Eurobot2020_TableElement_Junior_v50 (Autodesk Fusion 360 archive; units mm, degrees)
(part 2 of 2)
sketch "Sketch1" plane through (0, 0, 0) normal (1, 0, 0) x axis (0, 1, 0)
  line L1 (0, 5.6673) -> (0, 0)
  line L2 (0, 150) -> (0, 5.6673)
  line L3 (150, 0) -> (-150, 0)
  line L4 (0, -150) -> (0, 0)
  line L5 (25, -137.7498) -> (25, 137.7498)
  line L6 (-25, -137.7498) -> (-25, 137.7498)
  line L7 (15, -139.1941) -> (15, 139.1941)
  line L8 (-15, 139.1941) -> (-15, -139.1941)
  line L9 (15, 20) -> (-15, 20)
  line L10 (-15, -20) -> (15, -20)
  circle C1 centre (0, 0) radius 150
  arc A1 centre (0, 0) radius 140 clockwise from (-15, 139.1941) to (15, 139.1941)
  arc A2 centre (0, 0) radius 140 clockwise from (-25, -137.7498) to (-25, 137.7498)
  arc A3 centre (0, 0) radius 140 clockwise from (25, 137.7498) to (25, -137.7498)
  arc A4 centre (0, 0) radius 140 clockwise from (15, -139.1941) to (-15, -139.1941)
  point P1 (0, 0)
  point P2 (0, 0)
  point P3 (0, 0)
  point P5 (0, 150)
  point P6 (-150, 0)
  point P7 (150, 0)
  point P10 (0, 77.8337)
  point P11 (0, 0)
  point P12 (0, -150)
  point P13 (0, 0)
  point P18 (0, 0)
  point P17 (-25, -137.7498)
  point P19 (-25, -137.7498)
  point P20 (0, 0)
  point P15 (25, -137.7498)
  point P21 (25, -137.7498)
  point P24 (0, -75)
  point P25 (0, 0)
  point P26 (-15, 20)
  point P27 (15, 20)
  point P28 (15, -20)
  point P29 (-15, -20)
  coincident P1 P2
  coincident P1 P3
  vertical L1
  coincident C1 P5
  parallel L1 L2
  coincident C1 P6
  coincident C1 P7
  horizontal L3
  coincident P2 L3
  midpoint L2 P10
  coincident P2 P11
  coincident C1 P12
  perpendicular L3 L4
  coincident P1 P13
  vertical L6
  coincident P2 P18
  coincident P17 P19
  coincident P2 P20
  coincident P15 P21
  equal A1 A2
  equal A1 A3
  midpoint L4 P24
  coincident P2 P25
  tangent A3 A4
  perpendicular L3 L7
  parallel L6 L8
  coincident L8 P26
  coincident L7 P27
  perpendicular L7 L9
  coincident L7 P28
  coincident L8 P29
  perpendicular L8 L10
  dimension "d1" diameter C1 = 300
  dimension "d11" distance C1 A3 = 10
  dimension "d13" distance L5 L7 = 10
  dimension "d14" distance L6 L8 = 10
  dimension "d15" distance P18 L7 = 15
  dimension "d16" distance P20 L8 = 15
  dimension "d17" distance P13 L10 = 20
  dimension "d18" distance P2 L9 = 20
extrude "Extrude1" new body sketch "Sketch1" profile of C1 A1 L5 L6 A2 A3 A4 L7 L8 L9 L10 along normal blind 20
extrude "Extrude1" new body sketch "Sketch1" profile of C1 A1 L5 L6 A2 A3 A4 L7 L8 L9 L10 against normal blind 3
extrude "Extrude1" sketch "Sketch1" profile of C1 A1 L5 L6 A2 A3 A4 L7 L8 L9 L10 blind 3
as_built_joint "As-built1"
hole "Hole1" HoleDepth 70 HoleDiameter 7 TipAngle 118
sketch "Sketch3" plane through (0, 0, 0) normal (1, 0, 0) x axis (0, 1, 0)
  point P1 (0, 0)
  point P2 (0, 0)
  coincident P1 P2
hole "Hole2" HoleDepth 70 HoleDiameter 6 TipAngle 118
sketch "Sketch1" plane through (23, 0, 0) normal (1, 0, 0) x axis (0, 1, 0)
  circle C1 centre (0, 0) radius 150
  point P1 (0, 0)
  point P3 (0, 0)
  coincident P1 P3
hole "Hole2" HoleDepth 70 HoleDiameter 6 TipAngle 118 CSDiameter 14 CSAngle 90
sketch "Sketch2" plane through (0, 0, 0) normal (1, 0, 0) x axis (0, 1, 0)
  circle C1 centre (0, 0) radius 3.5
  circle C2 centre (0, 0) radius 2
  point P1 (0, 0)
  point P2 (0, 0)
  coincident P1 P2
  concentric C1 C2
  dimension "d55" diameter C1 = 7
  dimension "d56" diameter C2 = 4
extrude "Extrude1" new body sketch "Sketch2" along normal blind 20
as_built_joint "As-built2"
sketch "Sketch1" plane through (0, 0, 0) normal (0, 1, 0) x axis (1, 0, 0)
  line L1 (22.3531, 0) -> (-23.5815, 0)
  line L2 (22.3531, -4.2842) -> (22.3531, 0)
  line L3 (20, -1.7) -> (22.3531, -4.2842)
  line L4 (-23.5815, -1.7) -> (20, -1.7)
  line L5 (-23.5815, 0) -> (-23.5815, -1.7)
  line L6 (20, -150) -> (20, 150)
  point P1 (0, 0)
  point P5 (20, -1.7)
  horizontal L1
  perpendicular L1 L2
  perpendicular L2 L4
  coincident P1 L1
  coincident P5 L6
  vertical L5
  dimension "d59" distance L1 L4 = 1.7
revolve "Revolve1" sketch "Sketch1" AlongAngle 360
thread "Thread1" ThreadOffset 0 ThreadLength 21
sketch "Sketch2" plane through (0, 0, 0) normal (0, 1, 0) x axis (1, 0, 0)
  line L1 (-13.9609, -1.9748) -> (-23.5815, 0)
  line L2 (-23.5815, -1.9748) -> (-13.9609, -1.9748)
  line L3 (-23.5815, 0) -> (-23.5815, -1.9748)
  line L4 (-23.5815, 0) -> (0, 0)
  line L5 (-23.5815, 0.8397) -> (-23.5815, -0.8535)
  point P1 (0, 0)
  point P5 (0, 0)
  point P2 (-23.5815, 0)
  vertical L3
  horizontal L2
  coincident P1 P5
  horizontal L4
  coincident P2 L5
revolve "Revolve2" sketch "Sketch2" AlongAngle 360
offset_faces "OffsetFaces2" distance -0.43
offset_faces "OffsetFaces3" distance -1
sketch "Sketch3" plane through (22.3531, 0, 0) normal (1, 0, 0) x axis (0, 1, 0)
  line L1 (0, 2) -> (0, 0)
  line L2 (-0.4, 2) -> (0, 2)
  line L3 (-0.4, 0.4) -> (-0.4, 2)
  line L4 (-2, 0.4) -> (-0.4, 0.4)
  line L5 (-2, 0) -> (-2, 0.4)
  line L6 (0, 0) -> (-2, 0)
  line L7 (0.4, 0.4) -> (0.4, 2)
  line L8 (2, 0.4) -> (0.4, 0.4)
  line L9 (2, 0) -> (2, 0.4)
  line L10 (0.4, 2) -> (0, 2)
  line L11 (0.4, -2) -> (0, -2)
  line L12 (0.4, -0.4) -> (0.4, -2)
  line L13 (2, -0.4) -> (0.4, -0.4)
  line L14 (2, 0) -> (2, -0.4)
  line L15 (-0.4, -2) -> (0, -2)
  line L16 (-0.4, -0.4) -> (-0.4, -2)
  line L17 (-2, -0.4) -> (-0.4, -0.4)
  line L18 (-2, 0) -> (-2, -0.4)
  circle C1 centre (0, 0) radius 2.7989
  point P2 (0, 0)
  point P3 (0, 0)
  point P4 (0, 2)
  point P13 (0, 2)
  point P5 (-0.4, 2)
  point P9 (0.4, 2)
  point P6 (-0.4, 0.4)
  point P10 (0.4, 0.4)
  point P7 (-2, 0.4)
  point P11 (2, 0.4)
  point P8 (-2, 0)
  point P12 (2, 0)
  point P19 (0, -2)
  point P20 (-0.4, -2)
  point P21 (-0.4, -0.4)
  point P22 (-2, -0.4)
  point P23 (-2, 0)
  point P15 (0.4, -2)
  point P16 (0.4, -0.4)
  point P17 (2, -0.4)
  point P18 (2, 0)
  point P14 (0, -2)
  coincident P2 P3
  vertical L1
  perpendicular L1 L2
  perpendicular L2 L3
  perpendicular L1 L4
  perpendicular L2 L5
  horizontal L6
  equal L1 L6
  equal L2 L5
  symmetric P4 L1 P13
  symmetric L1 P5 P9
  symmetric L1 P6 P10
  symmetric L1 P7 P11
  symmetric L1 P8 P12
  symmetric P4 L6 P19
  symmetric P5 L6 P20
  symmetric P6 L6 P21
  symmetric P7 L6 P22
  symmetric P8 L6 P23
  symmetric L6 P9 P15
  symmetric L6 P10 P16
  symmetric L6 P11 P17
  symmetric L6 P12 P18
  symmetric L6 P13 P14
  dimension "d69" distance P4 P5 = 0.4
  dimension "d70" distance P7 P8 = 0.4
  dimension "d71" distance P3 P4 = 2
extrude "Extrude2" cut sketch "Sketch3" profile of L2 L3 L4 L5 L7 L8 L9 L10 L11 L12 L13 L14 L15 L16 L17 L18 against normal blind 1 taper -25
joint "Assemble1" alignAngle 0 alignOffsetX 0 alignOffsetY 0 alignOffsetZ 0.5
sketch "Sketch1" plane through (-3, 0, 0) normal (-1, 0, 0) x axis (0, -1, 0)
  circle C1 centre (0, 0) radius 3
  circle C2 centre (0, 0) radius 150
  circle C3 centre (0, 0) radius 5
  circle C4 centre (0, 0) radius 2
  point P1 (0, 0)
  point P3 (0, 0)
  coincident P1 P3
  concentric C1 C4
  dimension "d86" diameter C4 = 4
  dimension "d87" diameter C3 = 10
extrude "Extrude1" new body sketch "Sketch1" profile of C1 C3 C4 along normal blind 0.8
extrude "Extrude2" new body of existing geometry blind 0.8
as_built_joint "As-built3"
sketch "Sketch1" plane through (23, 0, 0) normal (1, 0, 0) x axis (0, 1, 0)
  circle C1 centre (0, 0) radius 150
extrude "Extrude1" new body sketch "Sketch1" along normal blind 0.3
decal "Decal1"
sketch "Sketch1" plane through (0, 0, 0) normal (1, 0, 0) x axis (0, 1, 0)
  line L1 (0, 32.5) -> (0, 0)
  line L2 (0, -127.5) -> (0, 0)
  line L3 (-15, 20) -> (15, 20)
  circle C1 centre (0, 32.5) radius 12.5
  circle C2 centre (0, -127.5) radius 12.5
  arc A1 centre (0, 0) radius 140 clockwise from (15, -139.1941) to (-15, -139.1941)
  point P1 (0, 0)
  point P2 (0, 0)
  point P3 (0, 32.5)
  point P4 (0, 32.5)
  point P5 (0, 0)
  point P6 (0, -127.5)
  point P7 (0, -127.5)
  point P8 (0, -140)
  point P9 (0, 20)
  coincident P1 P2
  vertical L1
  coincident P3 P4
  coincident P1 P5
  parallel L1 L2
  coincident P6 P7
  equal C1 C2
  coincident C2 P8
  coincident C1 P9
  coincident L1 P9
  coincident P9 L3
  coincident L2 P8
  coincident P8 A1
  dimension "d94" diameter C1 = 25
extrude "Extrude1" new body sketch "Sketch1" profile of C1 C2 along normal blind 18
as_built_joint "As-built4"
split_face "SplitFace1"
split_face "SplitFace1"
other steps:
split_face "SplitFace1"
split_face "SplitFace1"
create_component "CreateComponent1"
create_component "CreateComponent2"
create_component "CreateComponent3"
create_component "CreateComponent4"
create_component "CreateComponent5"
joint_origin "JointOrigin1" OffsetX 0 OffsetY 0 OffsetZ 0 AngleZ 0
joint_origin "JointOrigin1" OffsetX 0 OffsetY 0 OffsetZ 0 AngleZ 0
create_component "CreateComponent6"
create_component "CreateComponent7"
create_component "CreateComponent8"

design "Edge Beacon Right" references "EdgeBeacons_Base", "EdgeBeacons_LargeBorder", "EdgeBeacons_SmallBorder"
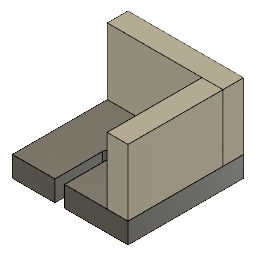
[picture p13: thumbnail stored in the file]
component_insert "Component Insert1"
ground "Ground1"
component_insert "Component Insert2"
component_insert "Component Insert4"
joint "Assemble1" OffsetX 0 OffsetY 0 OffsetZ 0 AngleZ 0 OffsetX 0 OffsetY 0 OffsetZ 0 AngleZ 0 alignAngle -90 alignOffsetX 0 alignOffsetY 0 alignOffsetZ 0
joint "Assemble2" OffsetX 0 OffsetY 0 OffsetZ 0 AngleZ 0 OffsetX 0 OffsetY 0 OffsetZ 0 AngleZ 0 alignAngle 0 alignOffsetX 0 alignOffsetY 0 alignOffsetZ 0

design "MiddleBeaconTop"
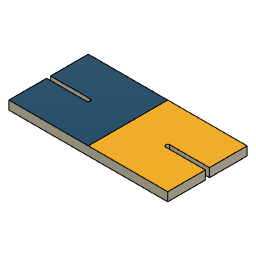
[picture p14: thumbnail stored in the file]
work_plane "WorkPlane1" AlongDistance 1000
sketch "Sketch1" plane through (0, 1000, 0) normal (0, 1, 0) x axis (1, 0, 0)
  line L1 (200, -100) -> (-200, -100)
  line L2 (200, 100) -> (200, -100)
  line L3 (-200, 100) -> (200, 100)
  line L4 (-200, -100) -> (-200, 100)
  line L5 (200, 100) -> (-200, -100)
  line L6 (-200, 100) -> (200, -100)
  line L7 (-100, -5) -> (-200, -5)
  line L8 (-200, 5) -> (-100, 5)
  line L9 (-100, 0) -> (-200, 0)
  line L10 (100, 5) -> (200, 5)
  line L11 (200, -5) -> (100, -5)
  line L12 (100, 0) -> (200, 0)
  arc A1 centre (-100, 0) radius 5 clockwise from (-100, 5) to (-100, -5)
  arc A2 centre (-200, 0) radius 5 clockwise from (-200, -5) to (-200, 5)
  arc A3 centre (100, 0) radius 5 clockwise from (100, -5) to (100, 5)
  arc A4 centre (200, 0) radius 5 clockwise from (200, 5) to (200, -5)
  point P6 (0, 0)
  point P1 (0, 0)
  point P11 (-200, 0)
  point P17 (200, 0)
  point P4 (200, 100)
  point P5 (-200, 100)
  point P3 (200, -100)
  point P12 (-100, 0)
  perpendicular L1 L2
  parallel L1 L3
  parallel L2 L4
  horizontal L1
  coincident L5 P6
  coincident L6 P6
  coincident P1 P6
  tangent L7 A1
  tangent A1 L8
  parallel L7 L8
  tangent L8 A2
  tangent L7 A2
  perpendicular L4 L9
  midpoint L4 P11
  tangent L10 A3
  tangent A3 L11
  parallel L10 L11
  tangent L11 A4
  tangent L10 A4
  perpendicular L2 L12
  midpoint L2 P17
  equal A1 A3
  equal L9 L12
  dimension "d2" distance P4 P5 = 400
  dimension "d3" distance P3 P4 = 200
  dimension "d4" distance P11 P12 = 100
  dimension "d5" radius A1 = 5
extrude "Extrude1" new body sketch "Sketch1" profile of L1 L2 L3 L4 L7 A1 L8 L10 A3 L11 against normal blind 22
work_plane "WorkPlane2"
split_face "SplitFace1"

design "MiddleBeaconVertSupport2"
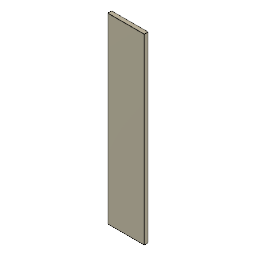
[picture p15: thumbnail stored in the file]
sketch "Sketch1"
  dimension "d1" = 1000
  dimension "d2" = 200
extrude "Extrude1" new body sketch "Sketch1" distance 22

design "manchonBleu"
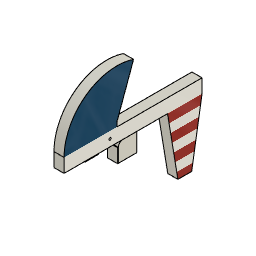
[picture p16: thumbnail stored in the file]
sketch "Sketch1" plane through (0, 0, 0) normal (1, 0, 0) x axis (0, 1, 0)
  line L1 (15, 15) -> (15, 25)
  line L2 (200, 15) -> (15, 15)
  line L3 (-100, -15) -> (125, -15)
  line L4 (-100, 15) -> (-100, -15)
  line L5 (200, 15) -> (200, -15)
  line L6 (177.5, -150) -> (200, -15)
  line L7 (147.5, -150) -> (177.5, -150)
  line L8 (125, -15) -> (147.5, -150)
  line L9 (0, 0) -> (200, 0)
  line L10 (15, 15) -> (-15, 15)
  line L11 (0, 15) -> (0, 0)
  line L12 (51.101, 124.1866) -> (15, 25)
  circle C1 centre (0, 0) radius 2.5
  circle C2 centre (15, 15) radius 115
  point P1 (0, 0)
  point P2 (0, 0)
  point P13 (200, 0)
  point P14 (0, 0)
  point P15 (0, 0)
  point P16 (0, 15)
  point P9 (-100, 15)
  point P5 (15, 15)
  point P17 (15, 15)
  point P18 (51.101, 124.1866)
  point P7 (125, -15)
  point P10 (200, -15)
  point P11 (177.5, -150)
  point P12 (147.5, -150)
  point P8 (-100, -15)
  point P4 (15, 25)
  coincident P1 P2
  perpendicular L1 L2
  horizontal L3
  perpendicular L3 L4
  vertical L5
  equal L4 L5
  parallel L3 L7
  equal L6 L8
  midpoint L5 P13
  coincident P1 P14
  horizontal L9
  coincident P1 P15
  midpoint L10 P16
  vertical L11
  coincident L2 P9
  horizontal L2
  horizontal L10
  equal L4 L10
  coincident P5 P17
  coincident P9 C2
  coincident C2 P18
  dimension "d1" diameter C1 = 5
  dimension "d2" distance P1 L4 = 100
  dimension "d4" distance P2 L5 = 200
  dimension "d8" distance P7 P10 = 75
  dimension "d9" distance P11 P12 = 30
  dimension "d11" distance P8 P9 = 30
  dimension "d12" distance P4 P5 = 10
  dimension "d22" distance L7 L9 = 150
  dimension "d23" angle L2 L12 = 70
  dimension "d36" OffsetX = 0
  dimension "d37" OffsetY = 0
  dimension "d38" OffsetZ = 0
  dimension "d39" AngleZ = 0
  dimension "d48" OffsetX = 0
  dimension "d49" OffsetY = 0
  dimension "d50" OffsetZ = 0
  dimension "d51" AngleZ = 0
extrude "Extrude1" new body sketch "Sketch1" profile of C1 L1 L2 L3 L4 L5 L6 L7 L8 C2 L12 along normal blind 22
sketch "Sketch1" plane through (0, 0, 0) normal (1, 0, 0) x axis (0, 0, -1)
  line L1 (55, 15) -> (15, 15)
  line L2 (55, 55) -> (55, 15)
  line L3 (15, 55) -> (55, 55)
  line L4 (15, 15) -> (15, 55)
  line L5 (15, -100) -> (15, 125)
  line L6 (25, 15) -> (15, 15)
  arc A1 centre (25, 25) radius 10 clockwise from (25, 15) to (15, 25)
  point P8 (25, 15)
  point P9 (15, 25)
  point P1 (0, 0)
  horizontal L1
  vertical L2
  horizontal L3
  vertical L4
  coincident L1 P8
  perpendicular L5 L6
  tangent L6 A1
  coincident L4 P9
  tangent L4 A1
  dimension "d24" distance P1 L1 = 15
  dimension "d25" distance P1 L4 = 15
  dimension "d26" distance P1 L5 = 15
  dimension "d27" distance L4 P8 = 10
  dimension "d28" distance L1 L3 = 40
  dimension "d29" distance L2 L4 = 40
  dimension "d32" OffsetX = 0
  dimension "d33" OffsetY = 0
  dimension "d34" OffsetZ = 0
  dimension "d35" AngleZ = 0
  dimension "d44" OffsetX = 0
  dimension "d45" OffsetY = 0
  dimension "d46" OffsetZ = 0
  dimension "d47" AngleZ = 0
extrude "Extrude1" new body sketch "Sketch1" profile of L1 L2 L3 L4 L5 A1 along normal blind 22
joint "Assemble1" alignAngle 0 alignOffsetX -25 alignOffsetY -28 alignOffsetZ 0
decal "Decal1"
decal "Decal2"
sketch "Sketch1" plane through (0, 18, 0) normal (0, -1, 0) x axis (1, 0, 0)
  line L1 (0, -55) -> (0, -25)
  line L2 (22, -55) -> (0, -55)
  line L3 (22, -25) -> (22, -55)
  line L4 (0, -25) -> (22, -25)
extrude "Extrude1" new body sketch "Sketch1" along normal blind 1.5 named "d52_1"
sketch "Sketch2" plane through (0, 0, -15) normal (0, 0, -1) x axis (1, 0, 0)
  line L1 (0, -125) -> (0, 100)
  line L2 (22, -125) -> (0, -125)
  line L3 (22, 100) -> (22, -125)
  line L4 (0, 100) -> (22, 100)
  line L5 (0, 55) -> (0, 25)
  line L6 (22, 55) -> (0, 55)
  line L7 (22, 25) -> (22, 55)
  line L8 (0, 25) -> (22, 25)
extrude "Extrude2" new body sketch "Sketch2" profile of L1 L3 L5 L6 L7 L8 along normal blind 1.5 named "d63_1"
joint_origin "JointOrigin1" OffsetX 0 named "d66_1" OffsetY 0 named "d67_1" OffsetZ 0 named "d68_1" AngleZ 0 named "d69_1"
joint_origin "JointOrigin2" OffsetX 0 named "d78_1" OffsetY 0 named "d79_1" OffsetZ 0 named "d80_1" AngleZ 0 named "d81_1"
remove_body "RemoveBody1"
joint "Assemble2" alignAngle 0 alignOffsetX 0 alignOffsetY 0 alignOffsetZ 0
base_feature "Base Feature"
joint "Assemble3" alignAngle 0 alignOffsetX 0 alignOffsetY 45 alignOffsetZ 0
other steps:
create_component "CreateComponent1"
create_component "CreateComponent2"
joint_origin "JointOrigin3" OffsetX 0 OffsetY 0 OffsetZ 0 AngleZ 0
joint_origin "JointOrigin3" OffsetX 0 OffsetY 0 OffsetZ 0 AngleZ 0
create_component "CreateComponent3"
joint_origin "JointOrigin1" OffsetX 0 OffsetY 0 OffsetZ 0 AngleZ 0
joint_origin "JointOrigin3" OffsetX 0 OffsetY 0 OffsetZ 0 AngleZ 0
joint_origin "JointOrigin4" OffsetX 0 OffsetY 0 OffsetZ 0 AngleZ 0
joint_origin "JointOrigin4" OffsetX 0 OffsetY 0 OffsetZ 0 AngleZ 0

design "Rocher"
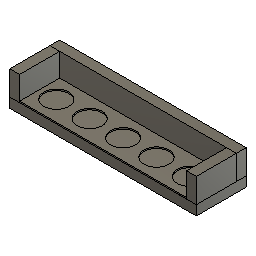
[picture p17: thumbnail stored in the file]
sketch "Sketch1" plane through (0, 0, 0) normal (0, 1, 0) x axis (1, 0, 0)
  line L1 (209.5, 0) -> (-209.5, 0)
  line L2 (209.5, 112) -> (209.5, 0)
  line L3 (-209.5, 112) -> (209.5, 112)
  line L4 (-209.5, 0) -> (-209.5, 112)
  point P6 (0, 0)
  horizontal L1
  vertical L2
  horizontal L3
  vertical L4
  coincident L1 P6
  dimension "d11" distance L2 L4 = 419 (= "375 mm + ( ( 22 * 2 ) * 1 mm )")
  dimension "d12" distance L2 P6 = 209.5 (= "d11 / 2")
  dimension "d13" distance L1 L3 = 112 (= "90 mm + 22 mm")
extrude "Extrude1" new body sketch "Sketch1" against normal blind 22
sketch "Sketch1" plane through (0, 0, 0) normal (0, 1, 0) x axis (-1, 0, 0)
  line L1 (-209.5, -112) -> (209.5, -112)
  line L2 (-209.5, -90) -> (-209.5, -112)
  line L3 (209.5, -90) -> (-209.5, -90)
  line L4 (209.5, -112) -> (209.5, -90)
  line L5 (-209.5, -112) -> (-209.5, 0)
  line L6 (209.5, 0) -> (209.5, -112)
  line L7 (209.5, -112) -> (-209.5, -112)
  horizontal L1
  vertical L2
  horizontal L3
  vertical L4
  collinear L2 L5
  collinear L4 L6
  collinear L1 L7
  dimension "d17" distance L1 L3 = 22
extrude "Extrude1" new body sketch "Sketch1" along normal blind 55
sketch "Sketch1" plane through (0, 0, 0) normal (0, 1, 0) x axis (-1, 0, 0)
  line L1 (-147, 0) -> (147, 0)
  line L2 (147, -90) -> (125, -90)
  line L3 (147, 0) -> (147, -90)
  line L4 (125, 0) -> (147, 0)
  line L5 (125, -90) -> (125, 0)
  line L6 (-147, 0) -> (147, 0)
  line L7 (147, -112) -> (-147, -112)
  line L8 (147, 0) -> (147, -112)
  line L9 (147, -90) -> (-147, -90)
  line L10 (147, 0) -> (147, -112)
  line L11 (-147, -112) -> (-147, 0)
  line L12 (147, -112) -> (-147, -112)
  horizontal L2
  vertical L3
  horizontal L4
  vertical L5
  collinear L4 L6
  collinear L3 L8
  collinear L2 L9
  dimension "d20" distance L3 L5 = 22
extrude "Extrude1" new body sketch "Sketch1" profile of L1 L2 L3 L4 L5 L6 L8 L9 L10 along normal blind 55
sketch "Sketch1" plane through (0, 0, 0) normal (0, 1, 0) x axis (-1, 0, 0)
  line L1 (209.5, 0) -> (209.5, -112)
  line L2 (-209.5, 0) -> (209.5, 0)
  line L3 (-209.5, -112) -> (-209.5, 0)
  line L4 (209.5, -112) -> (-209.5, -112)
  line L5 (-187.5, -90) -> (-209.5, -90)
  line L6 (-187.5, 0) -> (-187.5, -90)
  line L7 (-209.5, 0) -> (-187.5, 0)
  line L8 (-209.5, -90) -> (-209.5, 0)
  line L9 (209.5, -90) -> (-209.5, -90)
  horizontal L5
  vertical L6
  horizontal L7
  vertical L8
  collinear L2 L7
  collinear L5 L9
  collinear L3 L8
  dimension "d23" distance L6 L8 = 22
extrude "Extrude1" new body sketch "Sketch1" profile of L2 L3 L5 L6 L7 L8 L9 along normal blind 55
joint "Assemble1" alignAngle 0 alignOffsetX 0 alignOffsetY 0 alignOffsetZ 0
joint "Assemble2" alignAngle 0 alignOffsetX 0 alignOffsetY 0 alignOffsetZ 0
joint "Assemble3" alignAngle 0 alignOffsetX 0 alignOffsetY 0 alignOffsetZ 0
ground "Ground1"
sketch "Sketch1" plane through (0, 0, 0) normal (0, 1, 0) x axis (-1, 0, 0)
  line L1 (209.5, 0) -> (209.5, -112)
  line L2 (-209.5, 0) -> (209.5, 0)
  line L3 (-209.5, -112) -> (-209.5, 0)
  line L4 (209.5, -112) -> (-209.5, -112)
  line L5 (-209.5, -90) -> (209.5, -90)
  line L6 (187.5, -90) -> (187.5, 0)
  line L7 (-187.5, 0) -> (-187.5, -90)
  circle C1 centre (150, -45) radius 28
  circle C2 centre (75, -45) radius 28
  circle C3 centre (0, -45) radius 28
  circle C4 centre (-75, -45) radius 28
  circle C5 centre (-150, -45) radius 28
  point P12 (150, -45)
  point P13 (75, -45)
  point P14 (0, -45)
  point P15 (-75, -45)
  point P16 (-150, -45)
  dimension "d62" diameter C1 = 56
  dimension "d67" distance L6 P12 = 37.5
  dimension "d68" distance P12 P13 = 75 (= "d67 * 2")
  dimension "d69" distance P13 P14 = 75 (= "d68")
  dimension "d70" distance P14 P15 = 75 (= "d69")
  dimension "d72" distance L2 P12 = 45
  dimension "d73" distance L2 P13 = 45
  dimension "d74" distance L2 P14 = 45
  dimension "d75" distance L2 P15 = 45
  dimension "d90" diameter C5 = 56 (= "d62")
  dimension "d91" distance P15 P16 = 75
  dimension "d92" distance L7 P16 = 37.5
  dimension "d93" diameter C2 = 56 (= "d62")
  dimension "d94" diameter C3 = 56 (= "d62")
  dimension "d95" diameter C4 = 56
extrude "Extrude1" new body sketch "Sketch1" profile of L2 L5 L6 L7 C1 C2 C3 C4 C5 along normal blind 3
joint "Assemble4" alignAngle 180 alignOffsetX 0 alignOffsetY 0 alignOffsetZ 0
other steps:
create_component "CreateComponent1"
create_component "CreateComponent2"
create_component "CreateComponent3"
create_component "CreateComponent4"
joint_origin "JointOrigin1" OffsetX 0 OffsetY 0 OffsetZ 0 AngleZ 0
joint_origin "JointOrigin1" OffsetX 0 OffsetY 0 OffsetZ 0 AngleZ 0
joint_origin "JointOrigin1" OffsetX 0 OffsetY 0 OffsetZ 0 AngleZ 0
joint_origin "JointOrigin2" OffsetX 0 OffsetY 0 OffsetZ 0 AngleZ 0
joint_origin "JointOrigin1" OffsetX 0 OffsetY 0 OffsetZ 0 AngleZ 0
joint_origin "JointOrigin3" OffsetX 0 OffsetY 0 OffsetZ 0 AngleZ 0
create_component "CreateComponent5"
joint_origin "JointOrigin1" OffsetX 0 OffsetY 0 OffsetZ 0 AngleZ 0
joint_origin "JointOrigin2" OffsetX 0 OffsetY 0 OffsetZ 0 AngleZ 0

design "Balise Rouge"
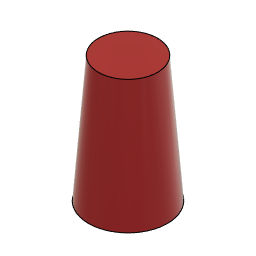
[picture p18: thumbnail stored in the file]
sketch "Sketch1" plane through (0, 0, 0) normal (1, 0, 0) x axis (0, 0, -1)
  line L1 (-36, 0) -> (0, 0)
  line L2 (-27, 115) -> (-36, 0)
  line L3 (0, 115) -> (-27, 115)
  line L4 (0, 0) -> (0, 115)
  line L5 (-25.6128, 113.5) -> (0, 113.5)
  line L6 (-34.4954, 0) -> (-25.6128, 113.5)
  line L7 (0, 0) -> (-34.4954, 0)
  point P1 (0, 0)
  point P2 (0, 0)
  point P6 (0, 0)
  point P7 (0, 113.5)
  point P10 (0, 0)
  point P4 (-27, 115)
  point P5 (0, 115)
  point P3 (-36, 0)
  coincident P1 P2
  horizontal L1
  parallel L1 L3
  coincident P1 P6
  perpendicular L1 L4
  coincident L4 P7
  perpendicular L4 L5
  coincident L4 P10
  perpendicular L4 L7
  collinear L1 L7
  parallel L2 L6
  dimension "d1" distance P4 P5 = 27 (= "( 54 / 2 ) * 1 mm")
  dimension "d2" distance L1 L3 = 115
  dimension "d3" distance P2 P3 = 36 (= "( 72 / 2 ) * 1 mm")
  dimension "d5" distance L3 L5 = 1.5
  dimension "d6" distance L2 L6 = 1.5
revolve "Revolve1" sketch "Sketch1" AlongAngle 360

design "taquet"
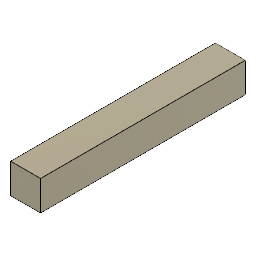
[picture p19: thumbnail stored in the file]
sketch "Sketch1" plane through (0, 0, 0) normal (0, 1, 0) x axis (1, 0, 0)
  line L1 (11, 150) -> (-11, 150)
  line L2 (11, 0) -> (11, 150)
  line L3 (11, 150) -> (-11, 0)
  line L4 (-11, 150) -> (-11, 0)
  point P1 (0, 0)
  horizontal L1
  vertical L2
  horizontal L3
  vertical L4
  coincident P1 L3
  dimension "d1" distance L2 L4 = 22
  dimension "d2" distance P1 L4 = 11 (= "d1 / 2")
  dimension "d3" = 150
extrude "Extrude1" new body sketch "Sketch1" along normal blind 22

design "ROUE_MINI_V3_ASSEMBLAGE" references "ROUE_V3"
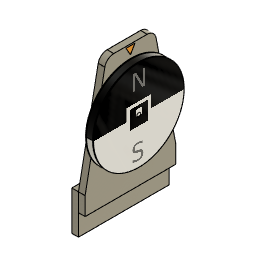
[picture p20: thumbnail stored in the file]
sketch "Sketch1" plane through (0, 0, 0) normal (1, 0, 0) x axis (0, 1, 0)
  line L1 (-150, 0) -> (0, 0)
  line L2 (0, 420) -> (-80, 420)
  line L3 (0, 0) -> (0, 420)
  line L4 (-150, 60) -> (-80, 420)
  line L5 (-150, 0) -> (-150, 60)
  line L6 (150, 0) -> (0, 0)
  line L7 (150, 0) -> (150, 60)
  line L8 (150, 60) -> (80, 420)
  line L9 (0, 420) -> (80, 420)
  point P1 (0, 0)
  point P2 (0, 0)
  point P6 (0, 0)
  point P8 (0, 0)
  point P3 (-150, 0)
  point P9 (150, 0)
  point P4 (-80, 420)
  point P11 (80, 420)
  point P5 (0, 420)
  point P12 (0, 420)
  point P7 (-150, 60)
  point P10 (150, 60)
  point P13 (0, 230)
  coincident P1 P2
  horizontal L1
  parallel L1 L2
  coincident P1 P6
  perpendicular L1 L3
  perpendicular L1 L5
  symmetric P2 L3 P8
  symmetric P3 L3 P9
  symmetric P4 L3 P11
  symmetric P5 L3 P12
  symmetric L3 P7 P10
  coincident L3 P13
  dimension "d1" distance P2 P3 = 150
  dimension "d2" distance P4 P5 = 80
  dimension "d3" distance P3 P7 = 60
  dimension "d4" distance L1 L2 = 420
  dimension "d5" distance L6 P13 = 230
extrude "Extrude1" new body sketch "Sketch1" profile of L1 L2 L4 L5 L6 L7 L8 L9 along normal blind 22
hole "Hole1" HoleDepth 100 HoleDiameter 3 TipAngle 118
fillet "Fillet1" radius 30
sketch "Sketch1" plane through (0, 0, 0) normal (-1, 0, 0) x axis (0, -1, 0)
  line L1 (-150, 60) -> (-84.7199, 395.7261)
  line L2 (-150, 0) -> (-150, 60)
  line L3 (150, 0) -> (-150, 0)
  line L4 (150, 60) -> (150, 0)
  line L5 (84.7199, 395.7261) -> (150, 60)
  line L6 (-55.2715, 420) -> (55.2715, 420)
  line L7 (-11, 213.2177) -> (-11, 0)
  line L8 (-86.7983, 136.8472) -> (-11, 136.8472)
  line L9 (-86.7983, 117.0762) -> (-86.7983, 136.8472)
  line L10 (-11, 117.0762) -> (-86.7983, 117.0762)
  line L11 (-11, 136.8472) -> (-11, 117.0762)
  line L12 (-13, 136.8472) -> (-11, 136.8472)
  line L13 (-13, 117.0762) -> (-13, 136.8472)
  line L14 (-11, 117.0762) -> (-13, 117.0762)
  line L15 (-11, 136.8472) -> (-11, 117.0762)
  circle C1 centre (0, 230) radius 1.5
  arc A1 centre (-55.2715, 390) radius 30 clockwise from (-84.7199, 395.7261) to (-55.2715, 420)
  arc A2 centre (55.2715, 390) radius 30 clockwise from (55.2715, 420) to (84.7199, 395.7261)
  point P13 (-11, 0)
  point P15 (-11, 136.8472)
  point P20 (-13, 117.0762)
  point P1 (0, 0)
  coincident L3 P13
  perpendicular L3 L7
  horizontal L8
  vertical L9
  horizontal L10
  vertical L11
  coincident L7 P15
  horizontal L12
  vertical L13
  horizontal L14
  vertical L15
  coincident L10 P20
  dimension "d31" distance L11 L13 = 2
  dimension "d32" distance P1 L7 = 11 (= "( 22 / 2 ) * 1 mm")
extrude "Extrude1" new body sketch "Sketch1" profile of L8 L9 L10 L11 L12 L13 L14 L15 along normal blind 2
extrude "Extrude2" add sketch "Sketch1" profile of L8 L10 L11 L12 L13 L14 L15 along normal blind 60
ground "Ground1"
sketch "Sketch1" plane through (0, 0, 0) normal (-1, 0, 0) x axis (0, -1, 0)
  line L1 (-150, 60) -> (-84.7199, 395.7261)
  line L2 (-150, 0) -> (-150, 60)
  line L3 (150, 0) -> (-150, 0)
  line L4 (150, 60) -> (150, 0)
  line L5 (84.7199, 395.7261) -> (150, 60)
  line L6 (-55.2715, 420) -> (55.2715, 420)
  line L7 (150, 0) -> (150, 60)
  line L8 (-150, 0) -> (-150, 60)
  line L9 (150, 60) -> (-150, 60)
  line L10 (150, -70) -> (150, 0)
  line L11 (-150, -70) -> (150, -70)
  line L12 (-150, 0) -> (-150, -70)
  circle C1 centre (0, 230) radius 1.5
  arc A1 centre (-55.2715, 390) radius 30 clockwise from (-84.7199, 395.7261) to (-55.2715, 420)
  arc A2 centre (55.2715, 390) radius 30 clockwise from (55.2715, 420) to (84.7199, 395.7261)
  point P15 (-150, 60)
  point P17 (-150, 60)
  point P13 (150, 60)
  point P18 (150, 60)
  point P14 (150, 0)
  point P19 (150, 0)
  point P7 (-150, 0)
  point P22 (-150, 0)
  point P20 (150, -70)
  coincident P15 P17
  coincident P13 P18
  coincident P14 P19
  perpendicular L3 L10
  perpendicular L10 L11
  coincident P7 P22
  vertical L12
  dimension "d37" distance P19 P20 = 70
extrude "Extrude1" new body sketch "Sketch1" profile of L2 L3 L4 L7 L8 L9 L10 L11 L12 along normal blind 22
joint "Assemble2" alignAngle 0 alignOffsetX 0 alignOffsetY 0 alignOffsetZ 0
joint "Assemble3" alignAngle 0 alignOffsetX 0 alignOffsetY 0 alignOffsetZ 0
sketch "Sketch1" plane through (22, 0, 0) normal (1, 0, 0) x axis (0, 1, 0)
  line L1 (-55.2715, 420) -> (55.2715, 420)
  line L2 (-150, 60) -> (-84.7199, 395.7261)
  line L3 (-150, 0) -> (-150, 60)
  line L4 (150, 0) -> (-150, 0)
  line L5 (150, 60) -> (150, 0)
  line L6 (84.7199, 395.7261) -> (150, 60)
  line L7 (0, 389.0192) -> (0, 420)
  line L8 (-15, 415) -> (0, 389.0192)
  line L9 (15, 415) -> (-15, 415)
  line L10 (0, 389.0192) -> (15, 415)
  arc A1 centre (55.2715, 390) radius 30 clockwise from (55.2715, 420) to (84.7199, 395.7261)
  arc A2 centre (-55.2715, 390) radius 30 clockwise from (-84.7199, 395.7261) to (-55.2715, 420)
  circle C1 centre (0, 230) radius 1.5
  point P13 (0, 420)
  point P14 (0, 389.0192)
  point P16 (15, 415)
  midpoint L1 P13
  perpendicular L1 L7
  perpendicular L7 L9
  equal L8 L10
  equal L8 L9
  dimension "d64" distance L1 L9 = 5
  dimension "d66" distance P14 P16 = 30
extrude "Extrude1" new body sketch "Sketch1" profile of L8 L9 L10 along normal blind 0.2
ground "Ground2"
ground "Ground3"
component_insert "Component Insert"
joint "Assemble4" OffsetX 0 OffsetY 0 OffsetZ 0 AngleZ 0 alignAngle 0 alignOffsetX 0 alignOffsetY 0 alignOffsetZ 0
ground "Ground4"
ground "Ground5"
joint "Assemble1" alignAngle 0 alignOffsetX 0 alignOffsetY -5 alignOffsetZ 0
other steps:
create_component "CreateComponent1"
create_component "CreateComponent3"
create_component "CreateComponent4"
joint_origin "JointOrigin1" OffsetX 0 OffsetY 0 OffsetZ 0 AngleZ 0
joint_origin "JointOrigin2" OffsetX 0 OffsetY 0 OffsetZ 0 AngleZ 0
joint_origin "JointOrigin2" OffsetX 0 OffsetY 0 OffsetZ 0 AngleZ 0
joint_origin "JointOrigin3" OffsetX 0 OffsetY 0 OffsetZ 0 AngleZ 0
create_component "CreateComponent1"
joint_origin "JointOrigin4" OffsetX 0 OffsetY 0 OffsetZ 0 AngleZ 0
joint_origin "JointOrigin1" OffsetX 0 OffsetY 0 OffsetZ 0 AngleZ 0
joint_origin "JointOrigin5" OffsetX 0 OffsetY 0 OffsetZ 0 AngleZ 0

design "MiddleBeaconVertSupport1"
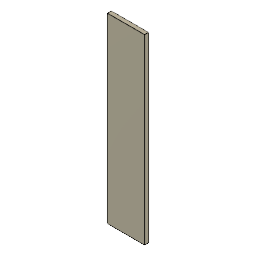
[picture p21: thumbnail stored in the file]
sketch "Sketch1"
  dimension "d1" = 978 (= "1000 mm - 22 mm")
  dimension "d2" = 200
extrude "Extrude1" new body sketch "Sketch1" distance 22

design "BorderSmall"
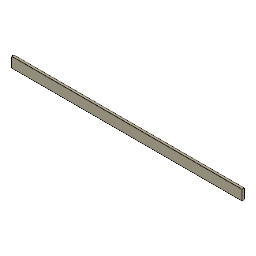
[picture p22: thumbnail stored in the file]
sketch "Sketch1" plane through (0, 0, 0) normal (0, 0, 1) x axis (1, 0, 0)
  line L1 (2044, 0) -> (0, 0)
  line L2 (2044, 92) -> (2044, 0)
  line L3 (0, 92) -> (2044, 92)
  line L4 (0, 0) -> (0, 92)
  point P1 (0, 0)
  point P2 (0, 0)
  point P3 (2044, 0)
  point P5 (0, 92)
  horizontal L1
  vertical L2
  horizontal L3
  vertical L4
  coincident P1 P2
  dimension "d1" distance P2 P3 = 2044 (= "2000 mm + 44 mm")
  dimension "d2" distance P2 P5 = 92 (= "70 mm + 22 mm")
extrude "Extrude1" new body sketch "Sketch1" along normal blind 22

design "ZoneRocheuse"
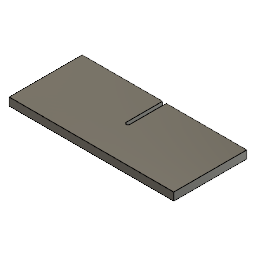
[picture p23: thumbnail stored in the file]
sketch "Sketch2" plane through (0, 0, 0) normal (0, 1, 0) x axis (1, 0, 0)
  line L1 (225, 200) -> (-225, 200)
  line L2 (225, 0) -> (225, 200)
  line L3 (-225, 0) -> (225, 0)
  line L4 (-225, 200) -> (-225, 0)
  line L5 (5, 200) -> (5, 100)
  line L6 (-5, 200) -> (-5, 100)
  circle C1 centre (0, 100) radius 5
  point P1 (0, 0)
  point P2 (0, 0)
  point P7 (0, 0)
  point P9 (5, 100)
  point P10 (5, 200)
  point P11 (-5, 100)
  point P12 (-5, 200)
  point P8 (0, 100)
  coincident P1 P2
  horizontal L1
  vertical L2
  horizontal L3
  vertical L4
  coincident L3 P7
  coincident C1 P9
  coincident L1 P10
  tangent C1 L5
  perpendicular L1 L5
  coincident C1 P11
  coincident L1 P12
  tangent C1 L6
  perpendicular L1 L6
  dimension "d19" distance L2 L4 = 450
  dimension "d20" distance L1 L3 = 200
  dimension "d21" distance L4 P7 = 225 (= "d19 / 2")
  dimension "d22" diameter C1 = 10
  dimension "d23" distance L1 P8 = 100
  dimension "d24" distance L4 P8 = 225 (= "d21")
  dimension "d9" diameter = 30
  dimension "d10" AlongDistance = 110
  dimension "d11" TaperAngle = 0
  dimension "d12" AgainstDistance = 130
  dimension "d13" Side2TaperAngle = 0
  dimension "d14" diameter = 30
  dimension "d15" AlongDistance = 125
  dimension "d16" TaperAngle = 0
  dimension "d17" AgainstDistance = 150
  dimension "d18" Side2TaperAngle = 0
extrude "Extrude2" new body sketch "Sketch2" against normal blind 22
